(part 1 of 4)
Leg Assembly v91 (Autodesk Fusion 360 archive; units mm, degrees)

design "Leg Assembly" references "Servo Actuator 2.0"
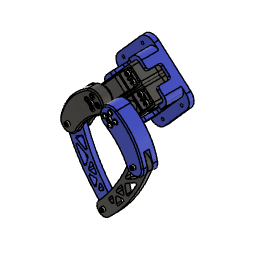
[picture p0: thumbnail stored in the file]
parameter "gapfit1" = 1 comment "gap on either side of the link 1 and 2 notch to accomodate link 3 and 4"
parameter "gapfit2" = 0.5 comment "gap between link 3 and 4"
parameter "gapfit3" = 0.5 comment "offset of space in the servos holder"
parameter "m3_diam" = 3.5 (= "3 mm + ( 0.5 mm )") comment "diameter used for m3 screw holes"
parameter "m3_locknut_width" = 5.9 (= "5.4 mm + ( 0.5 mm )") comment "lock nut width"
component_insert "Component Insert1"
component_insert "Component Insert2"
position "Position1"
position "Position2"
position "Position3"
base_feature "Base Feature1"
base_feature "Base Feature1"
base_feature "Base Feature1"
base_feature "Base Feature1"
extrude "Extrude1" add of existing geometry blind 3.556
extrude "Extrude2" add of existing geometry blind 1
sketch "Sketch1" plane through (0, 0, 13.9918) normal (0, 0, -1) x axis (1, 0, 0)
  circle C1 centre (0, -10.25) radius 4
  circle C2 centre (0, -10.25) radius 8.7625
  dimension "d5" = 4.7625
extrude "Extrude1" new body sketch "Sketch1" along normal blind 5.675 (= "0.125 in + 2.5 mm")
extrude "Extrude3" add of existing geometry blind 3.175
combine "Combine1"
extrude "Extrude2" cut of existing geometry blind -4.7
sketch "Sketch2" plane through (0, 0, 24.9956) normal (0, 0, 1) x axis (-1, 0, 0)
  line L1 (0.8395, -12.0586) -> (1.9866, -10.4203)
  line L2 (-1.9866, -10.0797) -> (0.8395, -12.0586)
  line L3 (-0.8395, -8.4414) -> (-1.9866, -10.0797)
  line L4 (1.9866, -10.4203) -> (-0.8395, -8.4414)
  line L5 (-1.9866, -10.0797) -> (-0.8395, -8.4414)
  line L6 (0.8395, -12.0586) -> (-1.9866, -10.0797)
  line L7 (1.9866, -10.4203) -> (0.8395, -12.0586)
  line L8 (-0.8395, -8.4414) -> (1.9866, -10.4203)
  circle C1 centre (0, -10.25) radius 4
split "Split1"
copy_paste_bodies "CutPasteBodies1"
copy_paste_bodies "CutPasteBodies1"
component_from_bodies "Body->Comp1"
extrude "Extrude3" new body of existing geometry blind 2.5
delete_face "DeleteFace1"
component_from_bodies "Body->Comp1"
copy_paste "CutPaste1"
sketch "Sketch1" plane through (0, 0, 0) normal (0, 0, 1) x axis (1, 0, 0)
  line L1 (-7.25, -8.75) -> (7.25, -8.75)
  line L2 (-7.25, 8.75) -> (-7.25, -8.75)
  line L3 (7.25, 8.75) -> (-7.25, 8.75)
  line L4 (7.25, -8.75) -> (7.25, 8.75)
  line L5 (-7.25, 8.75) -> (7.25, -8.75)
  line L6 (7.25, 8.75) -> (-7.25, -8.75)
  line L7 (0, 8.75) -> (0, -8.75)
  line L8 (-2.5, -2.35) -> (2.5, -2.35)
  line L9 (-2.5, 1.45) -> (-2.5, -2.35)
  line L10 (2.5, 1.45) -> (-2.5, 1.45)
  line L11 (2.5, -2.35) -> (2.5, 1.45)
  line L12 (-2.5, 1.45) -> (2.5, -2.35)
  line L13 (2.5, 1.45) -> (-2.5, -2.35)
  line L14 (7.25, -0.45) -> (-7.25, -0.45)
  line L15 (3.75, -8.75) -> (7.25, -5.25)
  line L16 (-3.75, -8.75) -> (-7.25, -5.25)
  arc A1 centre (0, 0.1797) radius 8.5703 clockwise from (-7.25, 4.75) to (7.25, 4.75)
  circle C1 centre (6, -0.45) radius 1.5
  circle C2 centre (-6, -0.45) radius 1.5
  point P6 (0, 0)
  point P1 (0, 0)
  point P7 (0, -8.75)
  point P8 (0, 8.75)
  point P13 (0, -0.45)
  point P14 (-7.25, -0.45)
  point P15 (7.25, -0.45)
  point P16 (7.25, 4.75)
  point P17 (-7.25, 4.75)
  point P19 (7.25, 4.75)
  point P18 (-7.25, 4.75)
  point P21 (7.25, -5.25)
  point P22 (3.75, -8.75)
  point P23 (7.25, -5.25)
  point P24 (3.75, -8.75)
  point P25 (-7.25, -5.25)
  point P26 (-3.75, -8.75)
  point P27 (6, -0.45)
  point P2 (7.25, -8.75)
  point P5 (7.25, 8.75)
  horizontal L1
  perpendicular L1 L2
  parallel L1 L3
  parallel L2 L4
  coincident L5 P6
  coincident L6 P6
  coincident P1 P6
  midpoint L1 P7
  midpoint L3 P8
  horizontal L8
  perpendicular L8 L9
  parallel L8 L10
  parallel L9 L11
  coincident L12 P13
  coincident L13 P13
  coincident L7 P13
  coincident L2 P14
  coincident L4 P15
  perpendicular L4 L14
  coincident P13 L14
  coincident L4 P16
  symmetric L7 P16 P17
  coincident P8 A1
  tangent L3 A1
  coincident P16 P19
  coincident P17 P18
  coincident L4 P21
  coincident L1 P22
  coincident P21 P23
  coincident P22 P24
  symmetric L7 P23 P25
  symmetric L7 P24 P26
  coincident L14 P27
  symmetric L7 C1 C2
  dimension "d1_1" distance P2 P5 = 17.5
  dimension "d2_1" distance L2 L4 = 14.5
  dimension "d3_1" distance L1 L8 = 6.4
  dimension "d4_1" distance L3 L10 = 7.3
  dimension "d5_1" distance L9 L11 = 5
  dimension "d6_1" distance P5 P16 = 4
  dimension "d7_1" distance P2 P21 = 3.5
  dimension "d8_1" distance P2 P22 = 3.5
  dimension "d9_1" diameter C1 = 3
  dimension "d10_1" distance L11 P27 = 3.5 (= "2 mm + 1.5 mm")
extrude "Extrude1" new body sketch "Sketch1" profile of L1 L2 L4 L8 L9 L10 L11 A1 L15 L16 C1 C2 against normal blind 1.7 named "d11_1"
extrude "Extrude2" new body sketch "Sketch1" profile of L8 L9 L10 L11 along normal blind 1.5 named "d13_1"
position "Position1"
position "Position2"
position "Position3"
position "Position4"
copy_paste "CutPaste2"
work_plane "WorkPlane1" AlongDistance -21
split "Split1"
combine "Combine1"
split "Split1"
remove_body "RemoveBody2"
extrude "Extrude1" add of existing geometry blind 2.2
extrude "Extrude2" add of existing geometry blind 1
extrude "Extrude3" cut of existing geometry blind -0.2
extrude "Extrude4" add of existing geometry blind 0.2
work_plane "WorkPlane2"
extrude "Extrude4" cut of existing geometry blind -0.2063 (= "( 2 mm - ( ( 1 / 16 ) * 1 in ) ) / -2")
extrude "Extrude5" cut of existing geometry blind -0.2063 (= "( 2 mm - ( ( 1 / 16 ) * 1 in ) ) / -2")
extrude "Extrude5" add of existing geometry blind 0.2063 (= "( 2 mm - ( ( 1 / 16 ) * 1 in ) ) / 2")
extrude "Extrude6" add of existing geometry blind 0.2063 (= "( 2 mm - ( ( 1 / 16 ) * 1 in ) ) / 2")
sketch "Sketch4" plane through (0, 0, 28) normal (0, 0, -1) x axis (1, 0, 0)
  line L1 (-1.6037, -23.3708) -> (-1.6037, 14.6292)
  line L2 (-0.9037, -30.2208) -> (-0.9037, -24.3248)
  line L3 (2.4963, -31.7208) -> (0.5963, -31.7208)
  line L4 (2.4963, -31.0175) -> (2.4963, -31.7208)
  line L5 (4.4963, -31.7208) -> (4.4963, -31.0175)
  line L6 (12.2963, -31.7208) -> (4.4963, -31.7208)
  line L7 (12.2963, -31.0175) -> (12.2963, -31.7208)
  line L8 (14.2963, -31.7208) -> (14.2963, -31.0175)
  line L9 (16.1963, -31.7208) -> (14.2963, -31.7208)
  line L10 (17.6963, -24.3248) -> (17.6963, -30.2208)
  line L11 (18.3963, 14.6292) -> (18.3963, -23.3708)
  line L12 (17.6963, 21.4792) -> (17.6963, 15.5831)
  line L13 (14.2963, 22.9792) -> (16.1963, 22.9792)
  line L14 (14.2963, 22.2758) -> (14.2963, 22.9792)
  line L15 (12.2963, 22.9792) -> (12.2963, 22.2758)
  line L16 (4.4963, 22.9792) -> (12.2963, 22.9792)
  line L17 (4.4963, 22.2758) -> (4.4963, 22.9792)
  line L18 (2.4963, 22.9792) -> (2.4963, 22.2758)
  line L19 (0.5963, 22.9792) -> (2.4963, 22.9792)
  line L20 (-0.9037, 15.5831) -> (-0.9037, 21.4792)
  line L21 (15.3963, 15.6292) -> (1.3963, 15.6292)
  line L22 (1.3963, 15.6292) -> (15.3963, 15.6292)
  line L23 (8.3963, -2.0612) -> (8.3963, 15.6292)
  line L24
  arc A1 centre (-0.6037, 14.6292) radius 1 clockwise from (-1.6037, 14.6292) to (-0.9037, 15.5831)
  arc A2 centre (-0.6037, -23.3708) radius 1 clockwise from (-0.9037, -24.3248) to (-1.6037, -23.3708)
  arc A3 centre (0.5963, -30.2208) radius 1.5 clockwise from (0.5963, -31.7208) to (-0.9037, -30.2208)
  arc A4 centre (3.4963, -29.1708) radius 2.1 clockwise from (2.4963, -31.0175) to (4.4963, -31.0175)
  arc A5 centre (13.2963, -29.1708) radius 2.1 clockwise from (12.2963, -31.0175) to (14.2963, -31.0175)
  arc A6 centre (16.1963, -30.2208) radius 1.5 clockwise from (17.6963, -30.2208) to (16.1963, -31.7208)
  arc A7 centre (17.3963, -23.3708) radius 1 clockwise from (18.3963, -23.3708) to (17.6963, -24.3248)
  arc A8 centre (17.3963, 14.6292) radius 1 clockwise from (17.6963, 15.5831) to (18.3963, 14.6292)
  arc A9 centre (16.1963, 21.4792) radius 1.5 clockwise from (16.1963, 22.9792) to (17.6963, 21.4792)
  arc A10 centre (13.2963, 20.4292) radius 2.1 clockwise from (14.2963, 22.2758) to (12.2963, 22.2758)
  arc A11 centre (3.4963, 20.4292) radius 2.1 clockwise from (4.4963, 22.2758) to (2.4963, 22.2758)
  arc A12 centre (0.5963, 21.4792) radius 1.5 clockwise from (-0.9037, 21.4792) to (0.5963, 22.9792)
  circle C1 centre (8.3963, 6.1292) radius 8.5
  point P48 (8.3963, 15.6292)
  point P50 (8.3963, 6.1292)
  midpoint L21 P48
  perpendicular L21 L23
  coincident L23 P50
  perpendicular L1 L24
  tangent C1 L24
  dimension "d32" diameter C1 = 17
  dimension "d33" distance L22 L24 = 1
extrude "Extrude4" new body sketch "Sketch4" profile of C1 along normal blind 27.9908
extrude "Extrude5" add of existing geometry blind 0.5092 (= "41.5 mm - 1.6138110236220502 in")
copy_paste_bodies "CutPasteBodies1"
sketch "Sketch5" plane through (0, 0, 28) normal (0, 0, -1) x axis (1, 0, 0)
  line L1 (-1.6037, -23.3708) -> (-1.6037, 14.6292)
  line L2 (-0.9037, -30.2208) -> (-0.9037, -24.3248)
  line L3 (2.4963, -31.7208) -> (0.5963, -31.7208)
  line L4 (2.4963, -31.0175) -> (2.4963, -31.7208)
  line L5 (4.4963, -31.7208) -> (4.4963, -31.0175)
  line L6 (12.2963, -31.7208) -> (4.4963, -31.7208)
  line L7 (12.2963, -31.0175) -> (12.2963, -31.7208)
  line L8 (14.2963, -31.7208) -> (14.2963, -31.0175)
  line L9 (16.1963, -31.7208) -> (14.2963, -31.7208)
  line L10 (17.6963, -24.3248) -> (17.6963, -30.2208)
  line L11 (18.3963, 14.6292) -> (18.3963, -23.3708)
  line L12 (17.6963, 21.4792) -> (17.6963, 15.5831)
  line L13 (14.2963, 22.9792) -> (16.1963, 22.9792)
  line L14 (14.2963, 22.2758) -> (14.2963, 22.9792)
  line L15 (12.2963, 22.9792) -> (12.2963, 22.2758)
  line L16 (4.4963, 22.9792) -> (12.2963, 22.9792)
  line L17 (4.4963, 22.2758) -> (4.4963, 22.9792)
  line L18 (2.4963, 22.9792) -> (2.4963, 22.2758)
  line L19 (0.5963, 22.9792) -> (2.4963, 22.9792)
  line L20 (-0.9037, 15.5831) -> (-0.9037, 21.4792)
  arc A1 centre (-0.6037, 14.6292) radius 1 clockwise from (-1.6037, 14.6292) to (-0.9037, 15.5831)
  arc A2 centre (-0.6037, -23.3708) radius 1 clockwise from (-0.9037, -24.3248) to (-1.6037, -23.3708)
  arc A3 centre (0.5963, -30.2208) radius 1.5 clockwise from (0.5963, -31.7208) to (-0.9037, -30.2208)
  arc A4 centre (3.4963, -29.1708) radius 2.1 clockwise from (2.4963, -31.0175) to (4.4963, -31.0175)
  arc A5 centre (13.2963, -29.1708) radius 2.1 clockwise from (12.2963, -31.0175) to (14.2963, -31.0175)
  arc A6 centre (16.1963, -30.2208) radius 1.5 clockwise from (17.6963, -30.2208) to (16.1963, -31.7208)
  arc A7 centre (17.3963, -23.3708) radius 1 clockwise from (18.3963, -23.3708) to (17.6963, -24.3248)
  arc A8 centre (17.3963, 14.6292) radius 1 clockwise from (17.6963, 15.5831) to (18.3963, 14.6292)
  arc A9 centre (16.1963, 21.4792) radius 1.5 clockwise from (16.1963, 22.9792) to (17.6963, 21.4792)
  arc A10 centre (13.2963, 20.4292) radius 2.1 clockwise from (14.2963, 22.2758) to (12.2963, 22.2758)
  arc A11 centre (3.4963, 20.4292) radius 2.1 clockwise from (4.4963, 22.2758) to (2.4963, 22.2758)
  arc A12 centre (0.5963, 21.4792) radius 1.5 clockwise from (-0.9037, 21.4792) to (0.5963, 22.9792)
split "Split1"
remove_body "RemoveBody1"
delete_face "DeleteFace1"
delete_face "DeleteFace2"
sketch "Sketch6" plane through (0, 0, 28) normal (0, 0, -1) x axis (1, 0, 0)
  line L1 (-0.9037, -24.3248) -> (17.6963, 15.5831)
  line L2 (-0.9037, 15.5831) -> (17.6963, -24.3248)
  line L3 (-0.8337, -23.6158) -> (17.6263, -23.6158)
  line L4 (-0.8337, 14.8742) -> (-0.8337, -23.6158)
  line L5 (17.6263, 14.8742) -> (-0.8337, 14.8742)
  line L6 (17.6263, -23.6158) -> (17.6263, 14.8742)
  line L7 (-0.8337, 14.8742) -> (17.6263, -23.6158)
  line L8 (17.6263, 14.8742) -> (-0.8337, -23.6158)
  line L9 (-4.0087, 18.0492) -> (-4.0087, -26.7908)
  line L10 (20.8013, 18.0492) -> (-4.0087, 18.0492)
  line L11 (20.8013, -26.7908) -> (20.8013, 18.0492)
  line L12 (-4.0087, -26.7908) -> (20.8013, -26.7908)
  point P2 (17.6963, 15.5831)
  point P6 (17.6963, 15.5831)
  point P4 (-0.9037, -24.3248)
  point P7 (-0.9037, -24.3248)
  point P3 (17.6963, -24.3248)
  point P8 (17.6963, -24.3248)
  point P5 (-0.9037, 15.5831)
  point P9 (-0.9037, 15.5831)
  point P10 (8.3963, -4.3708)
  point P15 (8.3963, -4.3708)
  point P13 (-0.8337, 14.8742)
  point P14 (17.6263, 14.8742)
  point P11 (17.6263, -23.6158)
  coincident P2 P6
  coincident P4 P7
  coincident P3 P8
  coincident P5 P9
  midpoint L1 P10
  horizontal L3
  perpendicular L3 L4
  parallel L3 L5
  parallel L4 L6
  coincident L7 P15
  coincident L8 P15
  coincident P10 P15
  dimension "d38" distance P13 P14 = 18.46
  dimension "d39" distance P11 P14 = 38.49
  dimension "d44" = -3.175 (= "( -1 / 8 ) * 1 in")
split "Split2"
split "Split3"
delete_face "DeleteFace3"
extrude "Extrude1" cut of existing geometry blind -33.02
delete_face "DeleteFace4"
extrude "Extrude2" cut of existing geometry blind -29.21
extrude "Extrude6" new body sketch "Sketch6" profile of L3 L4 L5 L6 L9 L12 L10 L11 along normal blind 28.4988
work_plane "WorkPlane3" AlongDistance -1.6
split "Split2"
sketch "Sketch7" plane through (0, 0, 26.4) normal (0, 0, 1) x axis (-1, 0, 0)
  line L1 (0.8337, -23.6158) -> (0.8337, 14.8742)
  line L2 (-17.6263, -23.6158) -> (0.8337, -23.6158)
  line L3 (-17.6263, 14.8742) -> (-17.6263, -23.6158)
  line L4 (0.8337, 14.8742) -> (-17.6263, 14.8742)
  line L5 (4.0087, -26.7908) -> (-20.8013, -26.7908)
  line L6 (4.0087, 18.0492) -> (4.0087, -26.7908)
  line L7 (-20.8013, 18.0492) -> (4.0087, 18.0492)
  line L8 (-20.8013, -26.7908) -> (-20.8013, 18.0492)
  line L9 (-20.8013, 6.1292) -> (4.0087, 6.1292)
  line L10 (-20.8013, -1.8708) -> (4.0087, -1.8708)
  circle C1 centre (-8.3963, 6.1292) radius 8.5
  circle C2 centre (-8.3963, 6.1292) radius 8.75
  point P12 (4.0087, 6.1292)
  point P13 (-20.8013, 6.1292)
  point P14 (4.0087, -1.8708)
  point P15 (-20.8013, -1.8708)
  coincident L6 P12
  coincident L8 P13
  perpendicular L8 L9
  coincident L6 P14
  coincident L8 P15
  perpendicular L8 L10
  dimension "d48" = 0.25
  dimension "d51" distance L9 L10 = 8
extrude "Extrude7" add sketch "Sketch7" profile of L1 L3 L4 C2 L10 against normal blind 26.8988
extrude "Extrude8" cut sketch "Sketch7" profile of L4 C2 against normal blind 38.1
offset_faces "OffsetFaces1" distance 0.75
fillet "Fillet3" radius 1.651
split "Split3"
remove_body "RemoveBody5"
mirror "Mirror1" mirrorStitchTolerance 0.1016
combine "Combine2"
component_from_bodies "Body->Comp1"
copy_paste_bodies "CutPasteBodies1"
mirror "Mirror1" mirrorStitchTolerance 0.1016
align "Align1"
extrude "Extrude1" add of existing geometry blind 6.35
extrude "Extrude9" new body of existing geometry blind 19.9898
copy_paste_bodies "CutPasteBodies2"
copy_paste "CutPaste3"
copy_paste_bodies "CutPasteBodies2"
sketch "Sketch8" plane through (0, 0, 19.9956) normal (0, 0, -1) x axis (1, 0, 0)
  line L1 (0.3963, -22.3708) -> (0.3963, -3.3708)
  line L2 (16.3963, -22.3708) -> (0.3963, -22.3708)
  line L3 (16.3963, -3.3708) -> (16.3963, -22.3708)
  line L4 (0.3963, -3.3708) -> (16.3963, -3.3708)
  line L5 (1.5713, -6.5458) -> (1.5713, -21.1958)
  line L6 (15.2213, -6.5458) -> (1.5713, -6.5458)
  line L7 (15.2213, -21.1958) -> (15.2213, -6.5458)
  line L8 (1.5713, -21.1958) -> (15.2213, -21.1958)
  line L9 (-4.0087, 18.0492) -> (20.8013, 18.0492)
  line L10 (-4.0087, -26.7908) -> (-4.0087, 18.0492)
  line L11 (20.8013, -26.7908) -> (-4.0087, -26.7908)
  line L12 (20.8013, 18.0492) -> (20.8013, -26.7908)
  line L13 (16.8763, -22.8658) -> (16.8763, -3.2059)
  line L14 (-0.0837, -22.8658) -> (16.8763, -22.8658)
  line L15 (-0.0837, -3.2059) -> (-0.0837, -22.8658)
  circle C1 centre (8.3963, -14.6208) radius 8
  circle C2 centre (8.3963, -14.6208) radius 8
  arc A1 centre (8.3963, 6.1292) radius 8.75 clockwise from (1.4656, 0.788) to (15.327, 0.788)
  arc A2 centre (16.6347, -0.2198) radius 1.651 clockwise from (15.93, -1.7129) to (15.327, 0.788)
  arc A3 centre (15.2253, -3.2059) radius 1.651 clockwise from (15.93, -1.7129) to (16.8763, -3.2059)
  arc A4 centre (1.5673, -3.2059) radius 1.651 clockwise from (-0.0837, -3.2059) to (0.8626, -1.7129)
  arc A5 centre (0.1579, -0.2198) radius 1.651 clockwise from (1.4656, 0.788) to (0.8626, -1.7129)
  circle C3 centre (8.3963, 6.1292) radius 8.5
  circle C4 centre (8.3963, 6.1292) radius 8.75
  dimension "d72" = 0.25
extrude "Extrude10" new body sketch "Sketch8" profile of L1 L2 L3 L4 L5 L6 L7 L8 C1 C2 A2 A3 L13 L14 L15 A4 A5 C4 along normal blind 5.0038
sketch "Sketch9" plane through (0, 0, 14.9918) normal (0, 0, -1) x axis (1, 0, 0)
  line L1 (-0.0837, -22.8658) -> (-0.0837, -3.2059)
  line L2 (16.8763, -22.8658) -> (-0.0837, -22.8658)
  line L3 (16.8763, -3.2059) -> (16.8763, -22.8658)
  circle C1 centre (8.3963, -14.6208) radius 8
  arc A1 centre (15.2253, -3.2059) radius 1.651 clockwise from (15.93, -1.7129) to (16.8763, -3.2059)
  arc A2 centre (16.6347, -0.2198) radius 1.651 clockwise from (15.93, -1.7129) to (15.327, 0.788)
  arc A3 centre (8.3963, 6.1292) radius 8.75 clockwise from (15.327, 0.788) to (1.4656, 0.788)
  arc A4 centre (0.1579, -0.2198) radius 1.651 clockwise from (1.4656, 0.788) to (0.8626, -1.7129)
  arc A5 centre (1.5673, -3.2059) radius 1.651 clockwise from (-0.0837, -3.2059) to (0.8626, -1.7129)
  arc A6 centre (8.3963, 6.1292) radius 8.75 clockwise from (15.327, 0.788) to (1.4656, 0.788)
  arc A7 centre (8.3963, 6.1292) radius 11.1625 clockwise from (17.2379, -0.6847) to (-0.4452, -0.6847)
  dimension "d73" = 2.4125 (= "0.125 in - 0.0300196850393694 in")
extrude "Extrude11" add sketch "Sketch9" profile of A1 A2 A3 A4 A5 A6 A7 along normal blind 15.4906
combine "Combine3"
delete_face "DeleteFace1"
delete_face "DeleteFace2"
fillet "Fillet1" radius 4.7625
sketch "Sketch10" plane through (0, 0, 8.3168) normal (0, 0, -1) x axis (1, 0, 0)
  circle C1 centre (8.3963, -14.6208) radius 4
  circle C2 centre (8.3963, -14.6208) radius 8
  circle C3 centre (8.3963, -14.6208) radius 9.5875
  dimension "d78" = 1.5875 (= "( 1 / 16 ) * 1 in")
extrude "Extrude7" cut sketch "Sketch10" along normal blind 15.24 and against normal blind 6.6802
extrude "Extrude8" add of existing geometry blind 0.0052 (= "2.047E-04 in")
sketch "Sketch11" plane through (0, 0, 14.9918) normal (0, 0, -1) x axis (1, 0, 0)
  line L1 (16.8763, -22.8658) -> (13.2892, -22.8658)
  line L2 (16.8763, -19.0941) -> (16.8763, -22.8658)
  line L3 (16.8763, -9.3559) -> (16.8763, -10.1476)
  line L4 (-0.0837, -10.1476) -> (-0.0837, -9.3559)
  line L5 (-0.0837, -22.8658) -> (-0.0837, -19.0941)
  line L6 (3.5034, -22.8658) -> (-0.0837, -22.8658)
  circle C1 centre (8.3963, -14.6208) radius 8
  arc A1 centre (8.3963, -14.6208) radius 9.5875 clockwise from (16.8763, -10.1476) to (16.8763, -19.0941)
  arc A2 centre (12.1138, -9.3559) radius 4.7625 clockwise from (11.0021, -4.7249) to (16.8763, -9.3559)
  arc A3 centre (8.3963, 6.1292) radius 11.1625 clockwise from (11.0021, -4.7249) to (5.7906, -4.7249)
  arc A4 centre (4.6788, -9.3559) radius 4.7625 clockwise from (-0.0837, -9.3559) to (5.7906, -4.7249)
  arc A5 centre (8.3963, -14.6208) radius 9.5875 clockwise from (-0.0837, -19.0941) to (-0.0837, -10.1476)
  arc A6 centre (8.3963, -14.6208) radius 9.5875 clockwise from (13.2892, -22.8658) to (3.5034, -22.8658)
  circle C2 centre (8.3963, -14.6208) radius 9.5875
  dimension "d85" = 1.5875 (= "( 1 / 16 ) * 1 in")
extrude "Extrude9" add sketch "Sketch11" profile of L1 L2 L3 A2 A3 A4 L4 L5 L6 C2 along normal blind 15.494
extrude "Extrude10" cut of existing geometry blind -0.0034 (= "-1.339E-04 in")
extrude "Extrude3" cut of existing geometry blind -0.508
extrude "Extrude11" cut of existing geometry blind -0.508
extrude "Extrude4" cut of existing geometry blind -1
offset_faces "OffsetFaces1" distance 1.5875 (= "( 1 / 16 ) * 1 in")
split "Split2"
delete_face "DeleteFace3"
combine "Combine4"
split "Split3"
sketch "Sketch12" plane through (0, 0, 4.8168) normal (0, 0, 1) x axis (-1, 0, 0)
  line L1 (-4.6463, -6.3208) -> (-1.1463, -9.8208)
  line L2 (-12.1463, -6.3208) -> (-4.6463, -6.3208)
  line L3 (-15.6463, -9.8208) -> (-12.1463, -6.3208)
  line L4 (-15.6463, -13.7917) -> (-15.6463, -9.8208)
  line L5 (-15.6463, -19.8208) -> (-15.6463, -15.45)
  line L6 (-1.1463, -15.45) -> (-1.1463, -19.8208)
  line L7 (-1.1463, -9.8208) -> (-1.1463, -13.7917)
  line L8 (-12.1463, -6.3208) -> (-15.6463, -9.8208)
  line L9 (-4.6463, -6.3208) -> (-12.1463, -6.3208)
  line L10 (-4.6463, -6.3208) -> (-1.1463, -9.8208)
  line L11 (-15.6463, -9.8208) -> (-15.6463, -19.8208)
  line L12 (-1.1463, -9.8208) -> (-1.1463, -19.8208)
  line L13 (-0.8963, -9.7173) -> (-0.8963, -19.8925)
  line L14 (-4.5428, -6.0708) -> (-0.8963, -9.7173)
  line L15 (-4.5428, -6.0708) -> (-12.2499, -6.0708)
  line L16 (-12.2499, -6.0708) -> (-15.8963, -9.7173)
  line L17 (-15.8963, -9.7173) -> (-15.8963, -19.8925)
  arc A1 centre (-14.3963, -14.6208) radius 1.5 clockwise from (-15.6463, -13.7917) to (-15.6463, -15.45)
  arc A2 centre (-8.3963, -15.2505) radius 8.5703 clockwise from (-1.1463, -19.8208) to (-15.6463, -19.8208)
  arc A3 centre (-2.3963, -14.6208) radius 1.5 clockwise from (-1.1463, -15.45) to (-1.1463, -13.7917)
  arc A4 centre (-8.3963, -15.2505) radius 8.5703 clockwise from (-1.1463, -19.8208) to (-15.6463, -19.8208)
  arc A5 centre (-8.3963, -15.2505) radius 8.8203 clockwise from (-0.8963, -19.8925) to (-15.8963, -19.8925)
  circle C1 centre (-8.3963, -14.6208) radius 9.5875
  point P15 (-15.6463, -19.8208)
  point P22 (-15.6463, -19.8208)
  point P18 (-15.6463, -9.8208)
  point P23 (-15.6463, -9.8208)
  point P16 (-1.1463, -19.8208)
  point P24 (-1.1463, -19.8208)
  point P21 (-1.1463, -9.8208)
  point P25 (-1.1463, -9.8208)
  coincident P15 P22
  coincident P18 P23
  coincident P16 P24
  coincident P21 P25
  dimension "d97" = 0.25
extrude "Extrude12" add sketch "Sketch12" profile of A5 L13 L14 L15 L16 L17 C1 against normal blind 4.8006
extrude "Extrude13" add of existing geometry blind 0.007 (= "2.756E-04 in")
split "Split4"
delete_face "DeleteFace4"
delete_face "DeleteFace5"
combine "Combine5"
extrude "Extrude14" add of existing geometry blind 1.4986
extrude "Extrude15" add of existing geometry blind 0.0014 (= "5.512E-05 in")
sketch "Sketch13" plane through (0, 0, 6.3168) normal (0, 0, 1) x axis (-1, 0, 0)
  line L1 (-15.8963, -9.7173) -> (-15.8963, -19.8925)
  line L2 (-12.2499, -6.0708) -> (-15.8963, -9.7173)
  line L3 (-4.5428, -6.0708) -> (-12.2499, -6.0708)
  line L4 (-0.8963, -9.7173) -> (-4.5428, -6.0708)
  line L5 (-0.8963, -19.8925) -> (-0.8963, -9.7173)
  line L6 (5.5962, 19.6367) -> (5.5962, -28.3783)
  line L7 (-22.3888, 19.6367) -> (5.5962, 19.6367)
  line L8 (-22.3888, -28.3783) -> (-22.3888, 19.6367)
  line L9 (5.5962, -28.3783) -> (-22.3888, -28.3783)
  line L10 (-3.6338, -52.7208) -> (-13.1588, -52.7208)
  line L11 (-3.6338, 23.4792) -> (-3.6338, -52.7208)
  line L12 (-13.1588, 23.4792) -> (-3.6338, 23.4792)
  line L13 (-13.1588, -52.7208) -> (-13.1588, 23.4792)
  line L14 (-3.6338, 23.4792) -> (-13.1588, -52.7208)
  line L15 (-13.1588, 23.4792) -> (-3.6338, -52.7208)
  arc A1 centre (-8.3963, -15.2505) radius 8.8203 clockwise from (-0.8963, -19.8925) to (-15.8963, -19.8925)
  circle C1 centre (-8.3963, 6.1292) radius 8.75
  circle C2 centre (-8.3963, -14.6208) radius 4
  point P19 (-8.3963, -14.6208)
  point P14 (-8.3963, -14.6208)
  point P15 (-13.1588, -52.7208)
  point P16 (-3.6338, -52.7208)
  point P18 (-13.1588, 23.4792)
  horizontal L10
  perpendicular L10 L11
  parallel L10 L12
  parallel L11 L13
  coincident L14 P19
  coincident L15 P19
  coincident P14 P19
  dimension "d106" distance P15 P16 = 9.525
  dimension "d107" distance P15 P18 = 76.2
extrude "Extrude16" cut sketch "Sketch13" profile of A1 L9 L11 L13 against normal blind 3.2004
extrude "Extrude17" cut sketch "Sketch13" profile of L7 C1 L11 L13 against normal blind 5.3086
extrude "Extrude18" cut of existing geometry blind -0.0002 (= "-7.873E-06 in")
extrude "Extrude19" add of existing geometry blind 0.0004 (= "1.574E-05 in")
combine "Combine1"
offset_faces "OffsetFaces2" distance 0.7937 (= "( 1 / 32 ) * 1 in")
extrude "Extrude20" add of existing geometry blind 2.175 (= "0.125 in - 1 mm")
sketch "Sketch14" plane through (0, 0, 28) normal (0, 0, 1) x axis (-1, 0, 0)
  line L1 (0.8337, 14.8742) -> (-17.6263, 14.8742)
  line L2 (0.8337, -23.6158) -> (0.8337, 14.8742)
  line L3 (-17.6263, -23.6158) -> (0.8337, -23.6158)
  line L4 (-17.6263, 14.8742) -> (-17.6263, -23.6158)
  line L5 (-22.3888, -28.3783) -> (-22.3888, 19.6367)
  line L6 (5.5962, -28.3783) -> (-22.3888, -28.3783)
  line L7 (5.5962, 19.6367) -> (5.5962, -28.3783)
  line L8 (-22.3888, 19.6367) -> (5.5962, 19.6367)
  line L9 (-17.6963, 15.5831) -> (0.9037, 15.5831)
  line L10 (0.9037, 15.5831) -> (-17.6963, 15.5831)
  line L11 (-18.3963, -23.3708) -> (-18.3963, 14.6292)
  line L12 (-18.3963, -17.3601) -> (-18.3963, -23.3708)
  line L13 (-18.3963, -4.3708) -> (-18.3963, -17.3601)
  line L14 (-18.3963, 14.6292) -> (-18.3963, -4.3708)
  line L15 (1.6037, 14.6292) -> (1.6037, -23.3708)
  line L16 (1.6037, -4.3708) -> (1.6037, 14.6292)
  line L17 (1.6037, -17.3601) -> (1.6037, -4.3708)
  line L18 (1.6037, -23.3708) -> (1.6037, -17.3601)
  line L19 (-17.6963, -24.3248) -> (0.9037, -24.3248)
  line L20 (0.9037, -24.3248) -> (-17.6963, -24.3248)
  arc A1 centre (-17.3963, 14.6292) radius 1 clockwise from (-18.3963, 14.6292) to (-17.6963, 15.5831)
  arc A2 centre (-17.3963, 14.6292) radius 1 clockwise from (-18.3963, 14.6292) to (-17.6963, 15.5831)
  arc A3 centre (0.6037, 14.6292) radius 1 clockwise from (0.9037, 15.5831) to (1.6037, 14.6292)
  arc A4 centre (0.6037, 14.6292) radius 1 clockwise from (0.9037, 15.5831) to (1.6037, 14.6292)
  arc A5 centre (0.6037, -23.3708) radius 1 clockwise from (1.6037, -23.3708) to (0.9037, -24.3248)
  arc A6 centre (0.6037, -23.3708) radius 1 clockwise from (1.6037, -23.3708) to (0.9037, -24.3248)
  arc A7 centre (-17.3963, -23.3708) radius 1 clockwise from (-17.6963, -24.3248) to (-18.3963, -23.3708)
  arc A8 centre (-17.3963, -23.3708) radius 1 clockwise from (-17.6963, -24.3248) to (-18.3963, -23.3708)
extrude "Extrude21" add sketch "Sketch14" profile of L5 L6 L7 L8 A1 A2 L9 L10 L11 L12 L13 L14 A3 A4 L15 L16 L17 L18 A5 A6 L19 L20 A7 A8 along normal blind 13.0048
split "Split5"
extrude "Extrude22" add of existing geometry blind 2
remove_body "RemoveBody3"
copy_paste "CutPaste1"
copy_paste_bodies "CutPasteBodies1"
remove_instance "RemoveInstance2"
split "Split6"
remove_body "RemoveBody4"
combine "Combine1"
offset_faces "OffsetFaces3" distance 4.93 (= "0.1315944881889787 in + ( 1 / 16 ) * 1 in")
sketch "Sketch16" plane through (0, 0, 28) normal (0, 0, 1) x axis (-1, 0, 0)
  line L1 (5.5962, 24.5667) -> (5.5962, -33.3083)
  line L2 (-22.3888, 24.5667) -> (5.5962, 24.5667)
  line L3 (-22.3888, -33.3083) -> (-22.3888, 24.5667)
  line L4 (5.5962, -33.3083) -> (-22.3888, -33.3083)
  line L5 (0.8337, 14.8742) -> (-17.6263, 14.8742)
  line L6 (0.8337, -23.6158) -> (0.8337, 14.8742)
  line L7 (-17.6263, -23.6158) -> (0.8337, -23.6158)
  line L8 (-17.6263, 14.8742) -> (-17.6263, -23.6158)
  arc A1 centre (-3.4963, 20.4292) radius 2.1 clockwise from (-2.4963, 22.2758) to (-4.4963, 22.2758)
  circle C1 centre (-3.4963, 20.4292) radius 1.5
  concentric A1 C1
  dimension "d141" diameter C1 = 3
work_plane "WorkPlane5"
chamfer "Chamfer1" distance 6.35
split "Split7"
sketch "Sketch17" plane through (0, 0, 28) normal (0, 0, 1) x axis (-1, 0, 0)
  line L1 (0.8337, 14.8742) -> (-17.6263, 14.8742)
  line L2 (0.8337, -23.6158) -> (0.8337, 14.8742)
  line L3 (-17.6263, -23.6158) -> (0.8337, -23.6158)
  line L4 (-17.6263, 14.8742) -> (-17.6263, -23.6158)
  line L5 (5.5962, -26.9583) -> (-0.7538, -33.3083)
  line L6 (5.5962, 18.2167) -> (5.5962, -26.9583)
  line L7 (-0.7538, 24.5667) -> (5.5962, 18.2167)
  line L8 (-16.0388, 24.5667) -> (-0.7538, 24.5667)
  line L9 (-22.3888, 18.2167) -> (-16.0388, 24.5667)
  line L10 (-22.3888, -26.9583) -> (-22.3888, 18.2167)
  line L11 (-16.0388, -33.3083) -> (-22.3888, -26.9583)
  line L12 (-0.7538, -33.3083) -> (-16.0388, -33.3083)
  arc A1 centre (-3.4963, 20.4292) radius 2.1 clockwise from (-2.4963, 22.2758) to (-4.4963, 22.2758)
  circle C1 centre (-3.4963, 20.4292) radius 2.2
  concentric A1 C1
  dimension "d149" diameter C1 = 4.4
extrude "Extrude26" cut sketch "Sketch17" profile of C1 against normal blind 6
mirror "Mirror4" mirrorStitchTolerance 0.1016
mirror "Mirror5" mirrorStitchTolerance 0.1016
sketch "Sketch1" plane through (0, 0, 0) normal (0, 0, 1) x axis (1, 0, 0)
  circle C1 centre (0, 0) radius 2.45
  circle C2 centre (0, 0) radius 1.5
  circle C3 centre (0, 0) radius 1.95
  point P1 (0, 0)
  point P2 (0, 0)
  coincident P1 P2
  concentric C1 C2
  concentric C1 C3
  dimension "d1_2" diameter C1 = 4.9
  dimension "d2_2" diameter C2 = 3
  dimension "d3_2" diameter C3 = 3.9
extrude "Extrude1" new body sketch "Sketch1" distance 0.7 (= "( 1.4 / 2 ) * 1 mm") named "d4_2"
extrude "Extrude2" add sketch "Sketch1" profile of C2 C3 distance 3.3 (= "5 mm - 1.7 mm") named "d6_2"
extrude "Extrude3" of existing geometry blind 1.7 named "d9_2"
extrude "Extrude4" add of existing geometry blind 1.7 named "d11_2"
mirror "Mirror1" mirrorStitchTolerance 0.1 named "d14_1"
extrude "Extrude5" new body sketch "Sketch1" profile of C2 C3 distance 3 named "d15_1"
extrude "Extrude6" sketch "Sketch1" blind -1.8 named "d18_1"
mirror "Mirror2" mirrorStitchTolerance 0.1 named "d21_1"
move "Move1"
copy_paste "CutPaste4"
remove_body "RemoveBody1"
align "Align1"
mirror "Mirror3" mirrorStitchTolerance 0.1016
mirror "Mirror4" mirrorStitchTolerance 0.1016
base_feature "Base Feature1"
base_feature "Base Feature1"
base_feature "Base Feature1"
base_feature "Base Feature1"
base_feature "Base Feature1"
base_feature "Base Feature1"
copy_paste "CutPaste5"
remove_instance "RemoveInstance4"
align "Align1"
mirror "Mirror1" mirrorStitchTolerance 0.1016
mirror "Mirror2" mirrorStitchTolerance 0.1016
sketch "Sketch18" plane through (0, 0, -2.1658) normal (0, 0, -1) x axis (1, 0, 0)
  line L1 (0.7538, -33.3083) -> (-5.5962, -26.9583)
  line L2 (16.0388, -33.3083) -> (0.7538, -33.3083)
  line L3 (22.3888, -26.9583) -> (16.0388, -33.3083)
  line L4 (22.3888, 18.2167) -> (22.3888, -26.9583)
  line L5 (16.0388, 24.5667) -> (22.3888, 18.2167)
  line L6 (0.7538, 24.5667) -> (16.0388, 24.5667)
  line L7 (-5.5962, 18.2167) -> (0.7538, 24.5667)
  line L8 (-5.5962, -26.9583) -> (-5.5962, 18.2167)
  line L9 (-5.5962, -26.9583) -> (0.7538, -33.3083)
  line L10 (-5.5962, 18.2167) -> (-5.5962, -26.9583)
  line L11 (0.7538, 24.5667) -> (-5.5962, 18.2167)
  line L12 (3.6338, 24.5667) -> (0.7538, 24.5667)
  line L13 (3.6338, 13.4695) -> (3.6338, 24.5667)
  line L14 (13.1588, 24.5667) -> (13.1588, 13.4695)
  line L15 (16.0388, 24.5667) -> (13.1588, 24.5667)
  line L16 (22.3888, 18.2167) -> (16.0388, 24.5667)
  line L17 (22.3888, -26.9583) -> (22.3888, 18.2167)
  line L18 (16.0388, -33.3083) -> (22.3888, -26.9583)
  line L19 (13.1588, -33.3083) -> (16.0388, -33.3083)
  line L20 (13.1588, -22.6746) -> (13.1588, -33.3083)
  line L21 (15.8963, -9.7173) -> (15.8963, -19.8925)
  line L22 (12.2499, -6.0708) -> (15.8963, -9.7173)
  line L23 (4.5428, -6.0708) -> (12.2499, -6.0708)
  line L24 (0.8963, -9.7173) -> (4.5428, -6.0708)
  line L25 (0.8963, -19.8925) -> (0.8963, -9.7173)
  line L26 (3.6338, -33.3083) -> (3.6338, -22.6746)
  line L27 (0.7538, -33.3083) -> (3.6338, -33.3083)
  line L28 (-5.5962, -26.9583) -> (22.3888, 18.2167)
  line L29 (-5.5962, 18.2167) -> (22.3888, -26.9583)
  line L30 (-1.1287, -25.0083) -> (17.9213, -25.0083)
  line L31 (-1.1287, 16.2667) -> (-1.1287, -25.0083)
  line L32 (17.9213, 16.2667) -> (-1.1287, 16.2667)
  line L33 (17.9213, -25.0083) -> (17.9213, 16.2667)
  line L34 (-1.1287, 16.2667) -> (17.9213, -25.0083)
  line L35 (17.9213, 16.2667) -> (-1.1287, -25.0083)
  arc A1 centre (8.3963, 6.1292) radius 8.75 clockwise from (13.1588, 13.4695) to (3.6338, 13.4695)
  arc A2 centre (8.3963, -15.2505) radius 8.8203 clockwise from (15.8963, -19.8925) to (13.1588, -22.6746)
  arc A3 centre (8.3963, -15.2505) radius 8.8203 clockwise from (3.6338, -22.6746) to (0.8963, -19.8925)
  circle C1 centre (17.9213, 16.2667) radius 2.2
  point P20 (22.3888, 18.2167)
  point P34 (22.3888, 18.2167)
  point P11 (-5.5962, -26.9583)
  point P35 (-5.5962, -26.9583)
  point P21 (22.3888, -26.9583)
  point P36 (22.3888, -26.9583)
  point P12 (-5.5962, 18.2167)
  point P37 (-5.5962, 18.2167)
  point P38 (8.3963, -4.3708)
  point P43 (8.3963, -4.3708)
  point P42 (17.9213, 16.2667)
  point P44 (17.9213, 16.2667)
  point P39 (17.9213, -25.0083)
  point P41 (-1.1287, 16.2667)
  coincident P20 P34
  coincident P11 P35
  coincident P21 P36
  coincident P12 P37
  midpoint L29 P38
  horizontal L30
  perpendicular L30 L31
  parallel L30 L32
  parallel L31 L33
  coincident L34 P43
  coincident L35 P43
  coincident P38 P43
  coincident P42 P44
  dimension "d164" distance P39 P42 = 41.275
  dimension "d165" distance P41 P42 = 19.05
  dimension "d166" diameter C1 = 4.4
extrude "Extrude27" cut sketch "Sketch18" profile of C1 against normal blind 6
mirror "Mirror6" mirrorStitchTolerance 0.1016
mirror "Mirror7" mirrorStitchTolerance 0.1016
copy_paste_bodies "CopyPasteBodies1"
move "Move2"
align "Align2"
mirror "Mirror5" mirrorStitchTolerance 0.1016
mirror "Mirror6" mirrorStitchTolerance 0.1016
offset_faces "OffsetFaces4" distance 0.7937 (= "( 1 / 32 ) * 1 in")
delete_face "DeleteFace8"
delete_face "DeleteFace9"
delete_face "DeleteFace10"
delete_face "DeleteFace11"
delete_face "DeleteFace12"
delete_face "DeleteFace13"
delete_face "DeleteFace14"
delete_face "DeleteFace15"
chamfer "Chamfer2" distance 6.35
sketch "Sketch19" plane through (0, 0, 8.3168) normal (0, 0, 1) x axis (-1, 0, 0)
  line L1 (-16.8326, -34.1021) -> (-23.1826, -27.7521)
  line L2 (-13.1588, -34.1021) -> (-16.8326, -34.1021)
  line L3 (-13.1588, -22.6746) -> (-13.1588, -34.1021)
  line L4 (-15.8963, -9.7173) -> (-15.8963, -19.8925)
  line L5 (-12.2499, -6.0708) -> (-15.8963, -9.7173)
  line L6 (-4.5428, -6.0708) -> (-12.2499, -6.0708)
  line L7 (-0.8963, -9.7173) -> (-4.5428, -6.0708)
  line L8 (-0.8963, -19.8925) -> (-0.8963, -9.7173)
  line L9 (-3.6338, -34.1021) -> (-3.6338, -22.6746)
  line L10 (0.0399, -34.1021) -> (-3.6338, -34.1021)
  line L11 (6.3899, -27.7521) -> (0.0399, -34.1021)
  line L12 (6.3899, 19.0104) -> (6.3899, -27.7521)
  line L13 (0.0399, 25.3604) -> (6.3899, 19.0104)
  line L14 (-3.6338, 25.3604) -> (0.0399, 25.3604)
  line L15 (-3.6338, 13.4695) -> (-3.6338, 25.3604)
  line L16 (-13.1588, 25.3604) -> (-13.1588, 13.4695)
  line L17 (-16.8326, 25.3604) -> (-13.1588, 25.3604)
  line L18 (-23.1826, 19.0104) -> (-16.8326, 25.3604)
  line L19 (-23.1826, -27.7521) -> (-23.1826, 19.0104)
  line L20 (-14.7463, -14.6208) -> (-2.0463, -14.6208)
  arc A1 centre (-8.3963, -15.2505) radius 8.8203 clockwise from (-13.1588, -22.6746) to (-15.8963, -19.8925)
  arc A2 centre (-8.3963, -15.2505) radius 8.8203 clockwise from (-0.8963, -19.8925) to (-3.6338, -22.6746)
  arc A3 centre (-8.3963, 6.1292) radius 8.75 clockwise from (-3.6338, 13.4695) to (-13.1588, 13.4695)
  circle C1 centre (-8.3963, -14.6208) radius 4
  arc A4 centre (-7.6763, -14.8049) radius 9.6671 clockwise from (-15.8963, -19.8925) to (-15.8963, -9.7173)
  arc A5 centre (-9.1163, -14.8049) radius 9.6671 clockwise from (-0.8963, -9.7173) to (-0.8963, -19.8925)
  point P26 (-8.3963, -14.6208)
  point P29 (-8.3963, -14.6208)
  point P6 (-15.8963, -19.8925)
  point P31 (-15.8963, -19.8925)
  point P8 (-15.8963, -9.7173)
  point P30 (-15.8963, -9.7173)
  point P11 (-0.8963, -9.7173)
  point P34 (-0.8963, -9.7173)
  point P12 (-0.8963, -19.8925)
  point P33 (-0.8963, -19.8925)
  point P27 (-2.0463, -14.6208)
  point P28 (-14.7463, -14.6208)
  perpendicular L4 L20
  coincident P26 P29
  midpoint L20 P29
  coincident P6 P31
  coincident P8 P30
  coincident P11 P34
  coincident P12 P33
  tangent A1 A4
  tangent A2 A5
  dimension "d179" distance P27 P28 = 12.7
extrude "Extrude28" cut sketch "Sketch19" profile of L4 L8 A4 A5 against normal blind 2
sketch "Sketch20" plane through (0, 0, 26.4) normal (0, 0, 1) x axis (-1, 0, 0)
  line L1 (-17.6263, 14.8742) -> (-8.6921, 14.8742)
  line L2 (-17.6263, -23.6158) -> (-17.6263, 14.8742)
  line L3 (0.8337, -23.6158) -> (-17.6263, -23.6158)
  line L4 (0.8337, 14.8742) -> (0.8337, -23.6158)
  line L5 (-8.1005, 14.8742) -> (0.8337, 14.8742)
  line L6 (0.0837, -22.8658) -> (0.0837, -3.2059)
  line L7 (-16.8763, -22.8658) -> (0.0837, -22.8658)
  line L8 (-16.8763, -3.2059) -> (-16.8763, -22.8658)
  line L9 (-16.8763, 12.104) -> (-16.8763, -3.2059)
  line L10 (0.0837, 11.1729) -> (0.0837, -3.2059)
  arc A1 centre (-8.3963, 6.1292) radius 8.75 clockwise from (-8.1005, 14.8742) to (-1.4656, 0.788)
  arc A2 centre (-0.1579, -0.2198) radius 1.651 clockwise from (-0.8626, -1.7129) to (-1.4656, 0.788)
  arc A3 centre (-1.5673, -3.2059) radius 1.651 clockwise from (-0.8626, -1.7129) to (0.0837, -3.2059)
  arc A4 centre (-15.2253, -3.2059) radius 1.651 clockwise from (-16.8763, -3.2059) to (-15.93, -1.7129)
  arc A5 centre (-16.6347, -0.2198) radius 1.651 clockwise from (-15.327, 0.788) to (-15.93, -1.7129)
  arc A6 centre (-8.3963, 6.1292) radius 8.75 clockwise from (-15.327, 0.788) to (-8.6921, 14.8742)
  point P16 (-16.8763, -3.2059)
  point P21 (-16.8763, -3.2059)
  point P12 (0.0837, -3.2059)
  point P23 (0.0837, -3.2059)
  coincident P16 P21
  tangent A4 L9
  coincident P12 P23
  tangent A3 L10
extrude "Extrude29" cut sketch "Sketch20" profile of A1 A2 A3 A4 A5 A6 L9 L10 against normal blind 6.4008
extrude "Extrude30" cut of existing geometry blind -0.0036 (= "-1.417E-04 in")
component_from_bodies "Body->Comp1"
component_from_bodies "Body->Comp2"
component_from_bodies "Body->Comp3"
sketch "Sketch21" plane through (0, 0, 8.3168) normal (0, 0, 1) x axis (-1, 0, 0)
  line L1 (-3.6338, -34.1021) -> (-3.6338, -22.6746)
  line L2 (0.0399, -34.1021) -> (-3.6338, -34.1021)
  line L3 (6.3899, -27.7521) -> (0.0399, -34.1021)
  line L4 (6.3899, 19.0104) -> (6.3899, -27.7521)
  line L5 (0.0399, 25.3604) -> (6.3899, 19.0104)
  line L6 (-3.6338, 25.3604) -> (0.0399, 25.3604)
  line L7 (-3.6338, 13.4695) -> (-3.6338, 25.3604)
  line L8 (-13.1588, 25.3604) -> (-13.1588, 13.4695)
  line L9 (-16.8326, 25.3604) -> (-13.1588, 25.3604)
  line L10 (-23.1826, 19.0104) -> (-16.8326, 25.3604)
  line L11 (-23.1826, -27.7521) -> (-23.1826, 19.0104)
  line L12 (-16.8326, -34.1021) -> (-23.1826, -27.7521)
  line L13 (-13.1588, -34.1021) -> (-16.8326, -34.1021)
  line L14 (-13.1588, -22.6746) -> (-13.1588, -34.1021)
  line L15 (-12.2499, -6.0708) -> (-15.8963, -9.7173)
  line L16 (-4.5428, -6.0708) -> (-12.2499, -6.0708)
  line L17 (-0.8963, -9.7173) -> (-4.5428, -6.0708)
  line L18 (-0.8963, -9.7173) -> (-0.8963, -19.8925)
  line L19 (-4.5428, -6.0708) -> (-0.8963, -9.7173)
  line L20 (-12.2499, -6.0708) -> (-4.5428, -6.0708)
  line L21 (-15.8963, -9.7173) -> (-12.2499, -6.0708)
  line L22 (-15.8963, -19.8925) -> (-15.8963, -9.7173)
  line L23 (-13.1588, -34.1021) -> (-13.1588, -22.6746)
  line L24 (-3.6338, -34.1021) -> (-13.1588, -34.1021)
  line L25 (-3.6338, -22.6746) -> (-3.6338, -34.1021)
  arc A1 centre (-9.1163, -14.8049) radius 9.6671 clockwise from (-0.8963, -9.7173) to (-0.8963, -19.8925)
  arc A2 centre (-8.3963, -15.2505) radius 8.8203 clockwise from (-0.8963, -19.8925) to (-3.6338, -22.6746)
  arc A3 centre (-8.3963, 6.1292) radius 8.75 clockwise from (-3.6338, 13.4695) to (-13.1588, 13.4695)
  arc A4 centre (-8.3963, -15.2505) radius 8.8203 clockwise from (-13.1588, -22.6746) to (-15.8963, -19.8925)
  arc A5 centre (-7.6763, -14.8049) radius 9.6671 clockwise from (-15.8963, -19.8925) to (-15.8963, -9.7173)
  arc A6 centre (-8.3963, -15.2505) radius 8.5703 clockwise from (-1.1463, -19.8208) to (-15.6463, -19.8208)
  arc A7 centre (-8.3963, -15.2505) radius 8.8203 clockwise from (-3.6338, -22.6746) to (-13.1588, -22.6746)
  arc A8 centre (-8.3963, -15.2505) radius 8.8203 clockwise from (-13.1588, -22.6746) to (-15.8963, -19.8925)
  arc A9 centre (-8.3963, -15.2505) radius 8.8203 clockwise from (-0.8963, -19.8925) to (-3.6338, -22.6746)
  point P22 (-13.1588, -22.6746)
  point P32 (-13.1588, -22.6746)
  point P5 (-3.6338, -22.6746)
  point P31 (-3.6338, -22.6746)
  coincident P22 P32
  coincident P5 P31
  tangent A4 A7
extrude "Extrude1" add sketch "Sketch21" profile of L1 L14 A7 L23 L24 L25 against normal blind 5.207
move_face "MoveFace1"
position "Position5"
sketch "Sketch22" plane through (0, 0, 8.3168) normal (0, 0, 1) x axis (-1, 0, 0)
  line L1 (0.1537, -10.7673) -> (-3.4928, -7.1208)
  line L2 (0.1537, -18.4744) -> (0.1537, -10.7673)
  line L3 (-3.4928, -22.1208) -> (0.1537, -18.4744)
  line L4 (0.0399, -34.1021) -> (-16.8326, -34.1021)
  line L5 (6.3899, -27.7521) -> (0.0399, -34.1021)
  line L6 (6.3899, 19.0104) -> (6.3899, -27.7521)
  line L7 (0.0399, 25.3604) -> (6.3899, 19.0104)
  line L8 (-3.6338, 25.3604) -> (0.0399, 25.3604)
  line L9 (-3.6338, 13.4695) -> (-3.6338, 25.3604)
  line L10 (-13.1588, 25.3604) -> (-13.1588, 13.4695)
  line L11 (-16.8326, 25.3604) -> (-13.1588, 25.3604)
  line L12 (-23.1826, 19.0104) -> (-16.8326, 25.3604)
  line L13 (-23.1826, -27.7521) -> (-23.1826, 19.0104)
  line L14 (-16.8326, -34.1021) -> (-23.1826, -27.7521)
  line L15 (-10.2963, -17.1208) -> (-10.2963, -12.1208)
  line L16 (-6.4963, -17.1208) -> (-10.2963, -17.1208)
  line L17 (-6.4963, -12.1208) -> (-6.4963, -17.1208)
  line L18 (-10.2963, -12.1208) -> (-6.4963, -12.1208)
  line L19 (-3.6338, 25.3604) -> (-3.6338, 13.4695)
  line L20 (-13.1588, 25.3604) -> (-3.6338, 25.3604)
  line L21 (-13.1588, 13.4695) -> (-13.1588, 25.3604)
  line L22 (-6.4963, -12.1208) -> (-10.2963, -17.1208)
  line L23 (-6.4963, -17.1208) -> (-10.2963, -12.1208)
  line L24 (11.7059, -11.4458) -> (-28.4985, -11.4458)
  line L25 (11.7059, -17.7958) -> (11.7059, -11.4458)
  line L26 (-28.4985, -17.7958) -> (11.7059, -17.7958)
  line L27 (-28.4985, -11.4458) -> (-28.4985, -17.7958)
  line L28 (11.7059, -17.7958) -> (-28.4985, -11.4458)
  line L29 (-28.4985, -17.7958) -> (11.7059, -11.4458)
  line L30 (14.7067, 9.3042) -> (-31.4993, 9.3042)
  line L31 (14.7067, 2.9542) -> (14.7067, 9.3042)
  line L32 (-31.4993, 2.9542) -> (14.7067, 2.9542)
  line L33 (-31.4993, 9.3042) -> (-31.4993, 2.9542)
  line L34 (14.7067, 2.9542) -> (-31.4993, 9.3042)
  line L35 (-31.4993, 2.9542) -> (14.7067, 9.3042)
  arc A1 centre (-9.026, -14.6208) radius 8.8203 clockwise from (-13.668, -22.1208) to (-13.668, -7.1208)
  arc A2 centre (-8.5804, -15.3408) radius 9.6671 clockwise from (-13.668, -7.1208) to (-3.4928, -7.1208)
  arc A3 centre (-8.5804, -13.9008) radius 9.6671 clockwise from (-3.4928, -22.1208) to (-13.668, -22.1208)
  arc A4 centre (-8.3963, 6.1292) radius 8.75 clockwise from (-3.6338, 13.4695) to (-13.1588, 13.4695)
  arc A5 centre (-8.3963, 6.1292) radius 8.75 clockwise from (-3.6338, 13.4695) to (-13.1588, 13.4695)
  circle C1 centre (-8.3963, 6.1292) radius 8.75
  point P25 (-10.2963, -17.1208)
  point P33 (-10.2963, -17.1208)
  point P27 (-6.4963, -12.1208)
  point P34 (-6.4963, -12.1208)
  point P24 (-10.2963, -12.1208)
  point P35 (-10.2963, -12.1208)
  point P26 (-6.4963, -17.1208)
  point P36 (-6.4963, -17.1208)
  point P37 (-8.3963, -14.6208)
  point P42 (-8.3963, -14.6208)
  point P47 (-8.3963, 6.1292)
  point P30 (-8.3963, 6.1292)
  point P28 (-13.1588, 13.4695)
  point P43 (-31.4993, 9.3042)
  point P46 (-31.4993, 2.9542)
  point P38 (-28.4985, -11.4458)
  point P41 (-28.4985, -17.7958)
  coincident P25 P33
  coincident P27 P34
  coincident P24 P35
  coincident P26 P36
  midpoint L23 P37
  horizontal L24
  perpendicular L24 L25
  parallel L24 L26
  parallel L25 L27
  coincident L28 P42
  coincident L29 P42
  coincident P37 P42
  horizontal L30
  perpendicular L30 L31
  parallel L30 L32
  parallel L31 L33
  coincident L34 P47
  coincident L35 P47
  coincident P30 P47
  concentric A5 C1
  coincident P28 C1
  dimension "d189" distance P43 P46 = 6.35
  dimension "d190" distance P38 P41 = 6.35
extrude "Extrude2" add sketch "Sketch22" profile of L9 L10 L19 L20 L21 C1 against normal blind 7.3152
extrude "Extrude3" cut sketch "Sketch22" profile of A4 L13 A5 L30 L32 C1 against normal blind 7.3152
extrude "Extrude4" cut sketch "Sketch22" profile of A1 L13 L24 L26 against normal blind 5.207
extrude "Extrude5" add of existing geometry blind 0.0064 (= "2.520E-04 in")
extrude "Extrude6" add of existing geometry blind 0.007 (= "2.756E-04 in")
sketch "Sketch23" plane through (0, 0, 8.3168) normal (0, 0, 1) x axis (-1, 0, 0)
  line L1 (-23.1826, 2.9542) -> (-16.55, 2.9542)
  line L2 (-23.1826, -11.4458) -> (-23.1826, 2.9542)
  line L3 (-17.255, -11.4458) -> (-23.1826, -11.4458)
  line L4 (0.1537, -10.7673) -> (-3.4928, -7.1208)
  line L5 (0.1537, -18.4744) -> (0.1537, -10.7673)
  line L6 (-3.4928, -22.1208) -> (0.1537, -18.4744)
  line L7 (-23.1826, -17.7958) -> (-17.255, -17.7958)
  line L8 (-23.1826, -27.7521) -> (-23.1826, -17.7958)
  line L9 (-16.8326, -34.1021) -> (-23.1826, -27.7521)
  line L10 (0.0399, -34.1021) -> (-16.8326, -34.1021)
  line L11 (6.3899, -27.7521) -> (0.0399, -34.1021)
  line L12 (6.3899, 19.0104) -> (6.3899, -27.7521)
  line L13 (0.0399, 25.3604) -> (6.3899, 19.0104)
  line L14 (-16.8326, 25.3604) -> (0.0399, 25.3604)
  line L15 (-23.1826, 19.0104) -> (-16.8326, 25.3604)
  line L16 (-23.1826, 9.3042) -> (-23.1826, 19.0104)
  line L17 (-16.55, 9.3042) -> (-23.1826, 9.3042)
  line L18 (6.3899, -27.7521) -> (0.0399, -34.1021)
  line L19 (6.3899, 19.0104) -> (6.3899, -27.7521)
  line L20 (0.0399, 25.3604) -> (6.3899, 19.0104)
  line L21 (-16.8326, 25.3604) -> (0.0399, 25.3604)
  line L22 (-23.1826, 19.0104) -> (-16.8326, 25.3604)
  line L23 (-23.1826, -27.7521) -> (-23.1826, 19.0104)
  line L24 (-16.8326, -34.1021) -> (-23.1826, -27.7521)
  line L25 (0.0399, -34.1021) -> (-16.8326, -34.1021)
  line L26 (0.8337, 14.8742) -> (-17.6263, 14.8742)
  line L27 (0.8337, -23.6158) -> (0.8337, 14.8742)
  line L28 (-17.6263, -23.6158) -> (0.8337, -23.6158)
  line L29 (-17.6263, 14.8742) -> (-17.6263, -23.6158)
  arc A1 centre (-8.3963, 6.1292) radius 8.75 clockwise from (-16.55, 9.3042) to (-16.55, 2.9542)
  arc A2 centre (-9.026, -14.6208) radius 8.8203 clockwise from (-17.255, -11.4458) to (-13.668, -7.1208)
  arc A3 centre (-8.5804, -15.3408) radius 9.6671 clockwise from (-13.668, -7.1208) to (-3.4928, -7.1208)
  arc A4 centre (-8.5804, -13.9008) radius 9.6671 clockwise from (-3.4928, -22.1208) to (-13.668, -22.1208)
  arc A5 centre (-9.026, -14.6208) radius 8.8203 clockwise from (-13.668, -22.1208) to (-17.255, -17.7958)
  circle C1 centre (-3.4963, 20.4292) radius 2.2
  circle C2 centre (-13.2963, 20.4292) radius 2.2
  circle C3 centre (-3.4963, -29.1708) radius 2.2
  circle C4 centre (-13.2963, -29.1708) radius 2.2
extrude "Extrude7" cut sketch "Sketch23" profile of C1 C2 C3 C4 against normal blind 6
delete_face "DeleteFace1"
remove_body "RemoveBody2"
remove_body "RemoveBody3"
remove_body "RemoveBody4"
remove_body "RemoveBody5"
delete_face "DeleteFace1"
delete_face "DeleteFace2"
delete_face "DeleteFace3"
delete_face "DeleteFace4"
position "Position6"
sketch "Sketch24" plane through (0, 0, 28) normal (0, 0, 1) x axis (-1, 0, 0)
  line L1 (6.3899, -27.7521) -> (0.0399, -34.1021)
  line L2 (6.3899, 19.0104) -> (6.3899, -27.7521)
  line L3 (0.0399, 25.3604) -> (6.3899, 19.0104)
  line L4 (-16.8326, 25.3604) -> (0.0399, 25.3604)
  line L5 (-23.1826, 19.0104) -> (-16.8326, 25.3604)
  line L6 (-23.1826, -27.7521) -> (-23.1826, 19.0104)
  line L7 (-16.8326, -34.1021) -> (-23.1826, -27.7521)
  line L8 (0.0399, -34.1021) -> (-16.8326, -34.1021)
  line L9 (0.8337, 14.8742) -> (-17.6263, 14.8742)
  line L10 (0.8337, -23.6158) -> (0.8337, 14.8742)
  line L11 (-17.6263, -23.6158) -> (0.8337, -23.6158)
  line L12 (-17.6263, 14.8742) -> (-17.6263, -23.6158)
  circle C1 centre (-3.4963, -29.1708) radius 1.5
  circle C2 centre (-3.4963, -29.1708) radius 1.5
  concentric C1 C2
  dimension "d205" diameter C2 = 3
extrude "Extrude1" cut sketch "Sketch24" profile of C2 against normal blind 43.18
mirror "Mirror1" mirrorStitchTolerance 0.1016
mirror "Mirror2" mirrorStitchTolerance 0.1016
extrude "Extrude8" cut of existing geometry blind -25.4
sketch "Sketch1" plane through (0, 0, 0) normal (0, 0, 1) x axis (1, 0, 0)
  circle C1 centre (0, 0) radius 2.45
  circle C2 centre (0, 0) radius 1.5
  circle C3 centre (0, 0) radius 1.95
  point P1 (0, 0)
  point P2 (0, 0)
  coincident P1 P2
  concentric C1 C2
  concentric C1 C3
  dimension "d1_3" diameter C1 = 4.9
  dimension "d2_3" diameter C2 = 3
  dimension "d3_3" diameter C3 = 3.9
extrude "Extrude1" new body sketch "Sketch1" distance 0.7 (= "( 1.4 / 2 ) * 1 mm") named "d4_3"
extrude "Extrude2" add sketch "Sketch1" profile of C2 C3 distance 3.3 (= "5 mm - 1.7 mm") named "d6_3"
extrude "Extrude3" of existing geometry blind 1.7 named "d9_3"
extrude "Extrude4" add of existing geometry blind 1.7 named "d11_3"
mirror "Mirror1" mirrorStitchTolerance 0.1 named "d14_2"
extrude "Extrude5" new body sketch "Sketch1" profile of C2 C3 distance 3 named "d15_2"
extrude "Extrude6" sketch "Sketch1" blind -1.8 named "d18_2"
mirror "Mirror2" mirrorStitchTolerance 0.1 named "d21_2"
move "Move1"
remove_body "RemoveBody1"
extrude "Extrude9" cut of existing geometry blind -0.4826 (= "10 mm - 0.4127007874015741 in")
position "Position7"
mirror "Mirror3" mirrorStitchTolerance 0.1016
mirror "Mirror4" mirrorStitchTolerance 0.1016
copy_paste "CutPaste6"
offset_faces "OffsetFaces1" distance -3.175
delete_face "DeleteFace2"
delete_face "DeleteFace3"
delete_face "DeleteFace4"
chamfer "Chamfer1" distance 4.7625
remove_instance "RemoveInstance1"
offset_faces "OffsetFaces2" distance -0.2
